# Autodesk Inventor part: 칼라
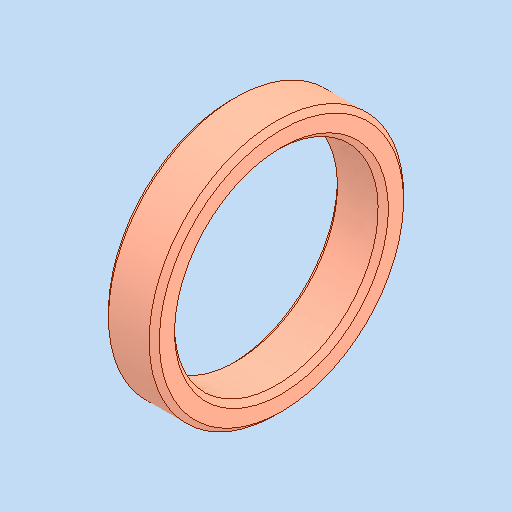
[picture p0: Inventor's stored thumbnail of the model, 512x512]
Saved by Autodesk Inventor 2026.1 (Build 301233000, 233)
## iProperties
Created: 2025-09
Part Number: 칼라
Material: 강철, 연강
Document SubType Name: Modeling
Designer: PC-30
Density: 7.85 g/cm^3
Appearance: 기본값
Author: jhkim
Sending System: Autodesk Inventor 2026
Preprocessor: ST-DEVELOPER v20.1
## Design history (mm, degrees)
feature "솔리드1"
node "솔리드2"
